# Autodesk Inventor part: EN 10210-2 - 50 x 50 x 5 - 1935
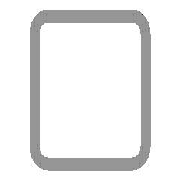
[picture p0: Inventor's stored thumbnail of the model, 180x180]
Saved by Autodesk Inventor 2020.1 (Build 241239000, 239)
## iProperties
_CCFamilyMember: 16
_CCFamilyDisplayName: DIN EN 10210-2 (USAS B17.1 quadratisch) - Rohrleitung — In Klammern angegebene Größen wurden aufgehoben
_FrameMemberDoc: Frame Member File
_Version: 15.0.0
_GetPNFromCC: 1
IsCustomPart: 1
Created: 2019-01
Part Number: EN 10210-2 - 50 x 50 x 5 - 1935
Material: Stahl, weich
Description: Rohrleitung
Document SubType Name: Modeling
Standard: DIN
Designer: lutzd
Standard Revision: 2006-07
Standards Organization: DIN
Language: de-DE
Size Designation: 50 x 50 x 5
Categories: <MemberInstance><Categories><Category DisplayName="Profile" InternalName="089c4875-fa83-4c05-b084-43b9cc11f5ed" Mnemonic="GRDR"><CategoryParameter DisplayName="
Stock Number: 50 x 50 x 5
Mass: 13260.6 g
Surface Area: 6568.91 cm^2
Volume: 1689.25 cm^3
Density: 7.85 g/cm^3
Appearance: Halbpoliert
G_W: 50,000 mm
G_H: 50,000 mm
DocNumber: ADSK-014213
Folder: .
Dimensions: 50x50x1935 mm
Mass: 13,261 kg
+915763CD-F418-4272-86B4-E58935006591+SCHNITTDETAIL1: Schnittwinkel 90,00 grd
+4F4A3D74-65AD-4673-B6F2-4A6164D70061+SCHNITTDETAIL2: Schnittwinkel 90,00 grd
G_L: 1935,000 mm
Title: Profil-Bauteil
Author: lutzd
Revision Number: -
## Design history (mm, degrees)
node "Startebene"
node "Endebene"
sketch "Skizze"
  geometry: L1 (-25, -17.5)-(-25, 17.5); L2 (-17.5, 25)-(17.5, 25); L3 (25, 17.5)-(25, -17.5); L4 (17.5, -25)-(-17.5, -25); L5 (-15, 20)-(15, 20); L6 (20, 15)-(20, -15); L7 (15, -20)-(-15, -20); L8 (-20, -15)-(-20, 15); L9 (0, 37.175)-(0, -37.175) reference; L10 (-37.175, 0)-(37.175, 0) reference; A1 r 7.5 centre (-17.5, -17.5) between (-25, -17.5) and (-17.5, -25); A2 r 7.5 centre (-17.5, 17.5) between (-17.5, 25) and (-25, 17.5); A3 r 7.5 centre (17.5, 17.5) between (25, 17.5) and (17.5, 25); A4 r 7.5 centre (17.5, -17.5) between (17.5, -25) and (25, -17.5); A5 r 5 centre (-15, -15) between (-20, -15) and (-15, -20); A6 r 5 centre (-15, 15) between (-15, 20) and (-20, 15); A7 r 5 centre (15, 15) between (20, 15) and (15, 20); A8 r 5 centre (15, -15) between (15, -20) and (20, -15)
  constraints: 16 end point, 16 point on circle, 16 tangent, 8 centre point, 6 equal radius, 4 parallel, 2 perpendicular, 2 other
  dimensions: "d7" = 7.5 radius of A1 (= G_IR); "d10" = 50 distance between parallel lines of L2 L4 (= G_H); "d11" = 50 distance between parallel lines of L1 L3 (= G_W); "d12" = 5 distance between parallel lines of L3 L6 (= G_T); "d15" = 25 distance between parallel lines of L2 L10 (= 0.5 x d10); "d16" = 25 distance between parallel lines of L9 L3 (= 0.5 x d11); "d19" = 5 radius of A5 (= G_T); "d20" = 5 distance between parallel lines of L4 L7 (= G_T)
extrude "Körper" new body sketch "Skizze" stored distance "d3" = 1935 (= G_L); taper "d4" = 0 deg
node "Driven Length"
  sketch "Sketch3"
    geometry: L1 (0, 0)-(10, 0) reference
    constraints: 2 end point, 1 horizontal
  workplane "Work Plane3"
  sketch "Sketch4"
    geometry: L1 (-2, 240)-(12, 240) reference; L2 (-2, 2175)-(12, 2175) reference
    dimensions: "d18" = 1935 distance between parallel lines of L1 L2 (derived)
workplane "Arbeitsebene4"
feature "Trennen1"
workplane "Arbeitsebene5"
feature "Trennen2"
sketch "Skizze5"
  geometry: L1 (810, -35)-(810, 0) reference; L2 (810, -17.5)-(1046, -17.5); 3 further points
  constraints: 4 end point, 1 coincident, 1 horizontal, 1 midpoint, 1 point on line, 1 vertical, 2 other
  dimensions: "d21" = 64 distance of point (982, -17.5) point (1046, -17.5); "d22" = 172 distance from line of point (982, -17.5) L1
hole "Bohrung1" sketch "Skizze5" at (1046, -17.5), (982, -17.5) diameter "d23" = 6.647; stored, may be unused: countersink angle "d27" = 90 deg, drill point angle "d29" = 118 deg; dims "d24" = 16, "d25" = 4, "d26" = 2, "d28" = 8
body "Solid1"
other parameters: "G_W" = 50 [user parameter; used in 1 equation term], "G_H" = 50 [user parameter; used in 1 equation term], "G_T" = 5 [user parameter; used in 3 equation terms], "G_IR" = 7.5 [user parameter; used in 1 equation term], "G_L" = 1935 (= d18) [user parameter; used in 1 equation term], "d14" = 2175 (= G_OFFSET_END + B_L), "B_L" = 2225 [user parameter; used in 1 equation term], "d17" = 90 deg
